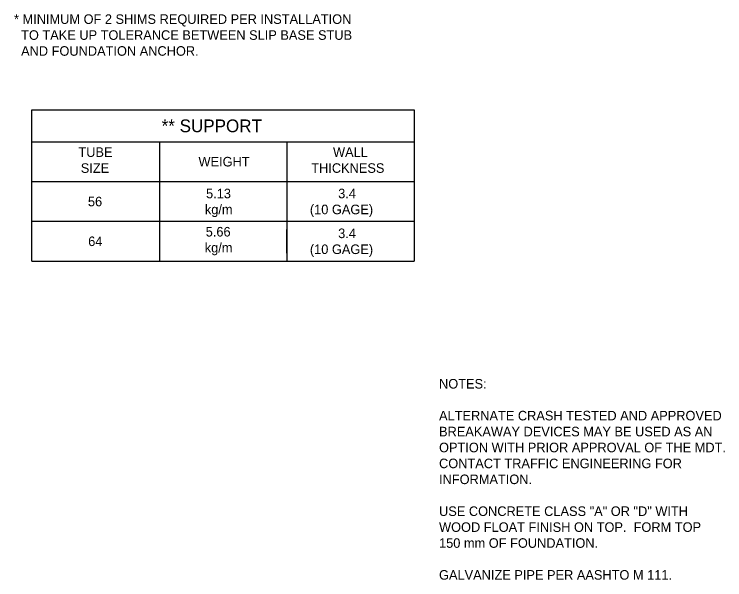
# Model space of a CAD drawing. Extents: x 49940 to 50043, y 49986 to 50011.
# Drawn here: x 50026.766 to 50031.226, y 49986.626 to 49990.177 of the extents above; entities that cross this region are included whole.
import ezdxf

# ---------------------------------------------------------------- set-up
doc = ezdxf.new("R2010")
doc.units = 0
doc.layers.add('Level 2', color=7, linetype='Continuous')

msp = doc.modelspace()

# ---------------------------------------------------------------- linework, layer by layer
at = {"layer": 'Level 2'}
for p, q in [((50026.8773, 49989.5764), (50029.2773, 49989.5764)), ((50026.8773, 49988.6264), (50026.8773, 49989.5764)), ((50029.2773, 49989.5764), (50029.2773, 49988.6264)), ((50026.8773, 49989.3764), (50029.2773, 49989.3764)), ((50027.6773, 49989.3764), (50027.6773, 49988.6264)), ((50028.4773, 49989.3764), (50028.4773, 49988.6264)), ((50026.8773, 49989.1264), (50029.2773, 49989.1264)), ((50027.6779, 49989.126), (50027.6779, 49989.126)), ((50028.4777, 49989.126), (50028.4777, 49989.126)), ((50028.4768, 49988.9763), (50028.4768, 49988.9763)), ((50028.4775, 49988.9768), (50028.4775, 49988.9768)), ((50029.2773, 49988.8764), (50026.8773, 49988.8764)), ((50027.6779, 49988.8764), (50027.6779, 49988.8764)), ((50028.4765, 49988.8764), (50028.4765, 49988.8764)), ((50028.4768, 49988.826), (50028.4768, 49988.826)), ((50028.4773, 49988.6764), (50028.4773, 49988.826)), ((50028.4772, 49988.6769), (50028.4772, 49988.6769)), ((50028.4775, 49988.6769), (50028.4775, 49988.6769)), ((50026.8773, 49988.6264), (50029.2773, 49988.6264))]:
    msp.add_line(p, q, dxfattribs=at)

# ---------------------------------------------------------------- texts
for s, height, p in [('* MINIMUM OF 2 SHIMS REQUIRED PER INSTALLATION', 0.06, (50026.7649, 49990.1165)), ('  TO TAKE UP TOLERANCE BETWEEN SLIP BASE STUB', 0.06, (50026.7649, 49990.0165)), ('  AND FOUNDATION ANCHOR.', 0.06, (50026.7649, 49989.9165)), ('** SUPPORT', 0.0799, (50027.6917, 49989.4364)), ('TUBE', 0.06, (50027.1692, 49989.2813)), ('WALL', 0.06, (50028.7673, 49989.2813)), ('WEIGHT', 0.06, (50027.9228, 49989.2214)), ('SIZE', 0.06, (50027.1841, 49989.1813)), ('THICKNESS', 0.06, (50028.6308, 49989.1813)), ('5.13', 0.06, (50027.9705, 49989.0215)), ('3.4', 0.06, (50028.7996, 49989.0214)), ('56', 0.06, (50027.229, 49988.9712)), ('kg/m', 0.06, (50027.9629, 49988.9215)), ('(10 GAGE)', 0.06, (50028.6221, 49988.9214)), ('5.66', 0.06, (50027.9683, 49988.7815)), ('3.4', 0.06, (50028.7996, 49988.7714)), ('64', 0.06, (50027.2306, 49988.7214)), ('kg/m', 0.06, (50027.9623, 49988.6815)), ('(10 GAGE)', 0.06, (50028.6221, 49988.6714)), ('NOTES:', 0.06, (50029.4328, 49987.8267)), ('ALTERNATE CRASH TESTED AND APPROVED', 0.06, (50029.4328, 49987.6267)), ('BREAKAWAY DEVICES MAY BE USED AS AN', 0.06, (50029.4328, 49987.5267)), ('OPTION WITH PRIOR APPROVAL OF THE MDT.', 0.06, (50029.4328, 49987.4267)), ('CONTACT TRAFFIC ENGINEERING FOR', 0.06, (50029.4328, 49987.3267)), ('INFORMATION.', 0.06, (50029.4328, 49987.2267)), ('USE CONCRETE CLASS "A" OR "D" WITH', 0.06, (50029.4328, 49987.0267)), ('WOOD FLOAT FINISH ON TOP.  FORM TOP', 0.06, (50029.4328, 49986.9267)), ('150 mm OF FOUNDATION.', 0.06, (50029.4328, 49986.8267)), ('GALVANIZE PIPE PER AASHTO M 111.', 0.06, (50029.4328, 49986.6267))]:
    msp.add_text(s, height=height, dxfattribs=at).set_placement(p)

doc.saveas('drawing.dxf')
